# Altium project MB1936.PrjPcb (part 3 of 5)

## Sheet Power_MPU.SchDoc: Power MPU
size A3; Date: Not used; ApprovedBy: Not used; CheckedBy: Not used; Author: Not used; CompanyName: STMicroelectronics; DrawnBy: Not used; Engineer: Not used; Organization: Not used; Address1: Not used; Address2: Not used; Address3: Not used; Address4: Not used; DocumentNumber: Not used; Revision: Not used; SheetNumber: 5; SheetTotal: 18
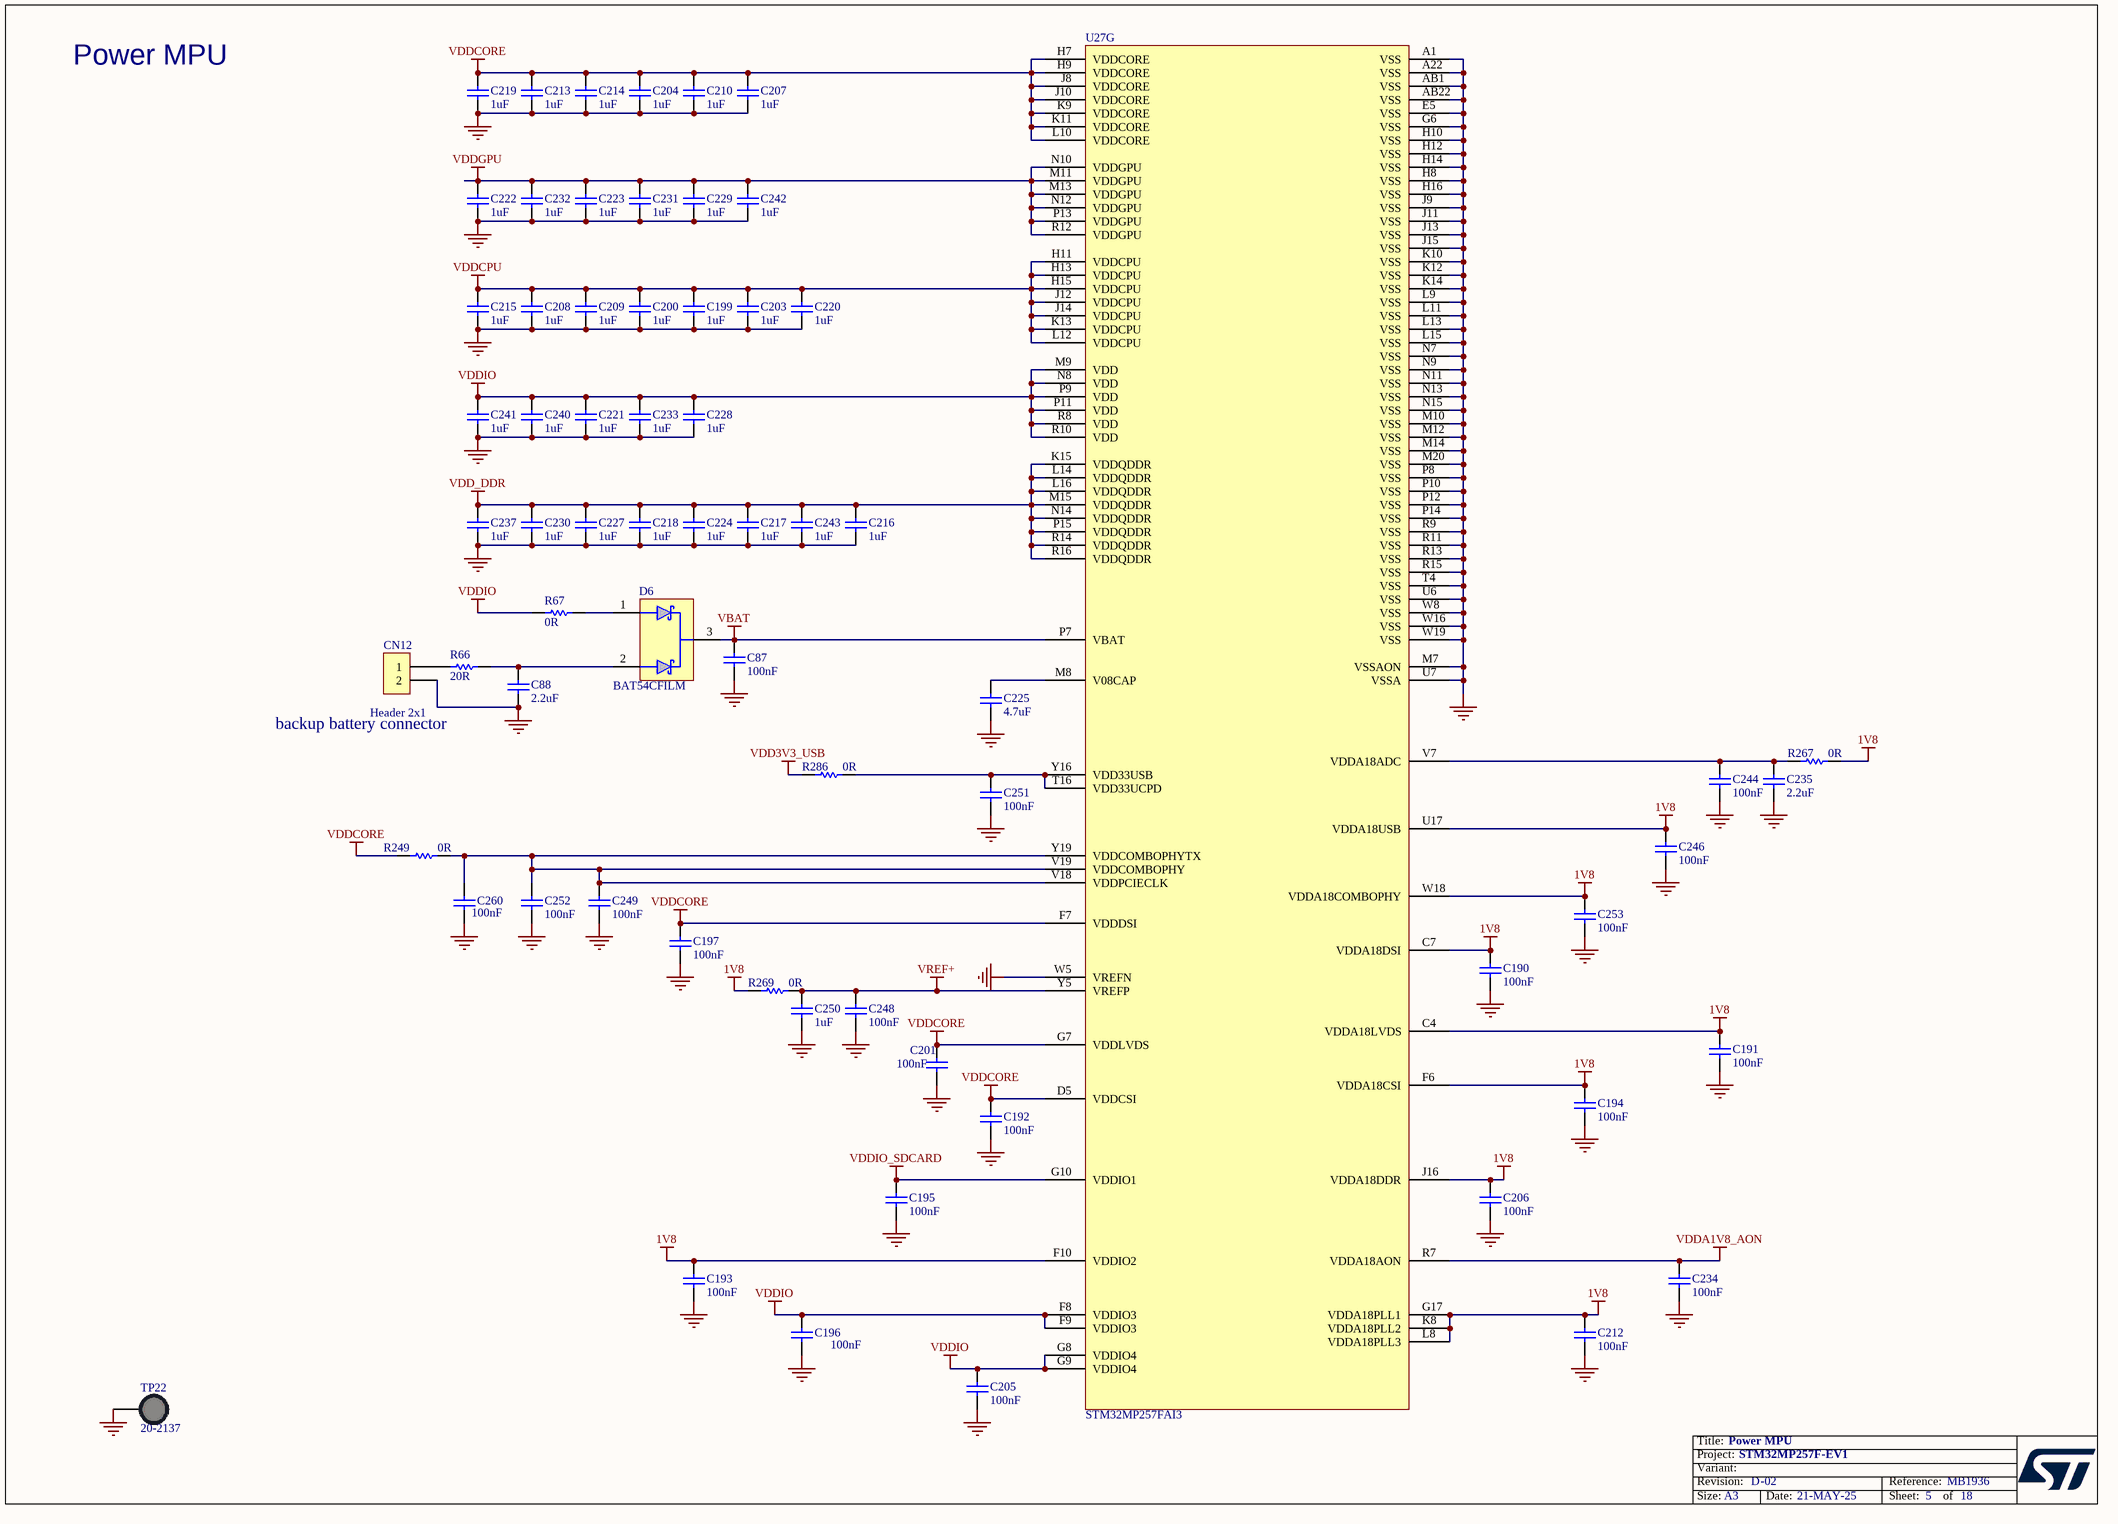
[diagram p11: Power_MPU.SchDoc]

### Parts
C87  value 100nF  [C0402]
C88  value 2.2uF  [C0402]  (hidden comment: Capacitor)
C190  value 100nF  [C0201_MURATA_GRM033_H0P3]  (hidden comment: Capacitor)
C191  value 100nF  [C0201_MURATA_GRM033_H0P3]  (hidden comment: Capacitor)
C192  value 100nF  [C0201_MURATA_GRM033_H0P3]  (hidden comment: Capacitor)
C193  value 100nF  [C0201_MURATA_GRM033_H0P3]  (hidden comment: Capacitor)
C194  value 100nF  [C0201_MURATA_GRM033_H0P3]  (hidden comment: Capacitor)
C195  value 100nF  [C0201_MURATA_GRM033_H0P3]  (hidden comment: Capacitor)
C196  value 100nF  [C0201_MURATA_GRM033_H0P3]  (hidden comment: Capacitor)
C197  value 100nF  [C0201_MURATA_GRM033_H0P3]  (hidden comment: Capacitor)
C199  value 1uF  [C0201_MURATA_GRM033_H0P3]  (hidden comment: Capacitor)
C200  value 1uF  [C0201_MURATA_GRM033_H0P3]  (hidden comment: Capacitor)
C201  value 100nF  [C0201_MURATA_GRM033_H0P3]  (hidden comment: Capacitor)
C203  value 1uF  [C0201_MURATA_GRM033_H0P3]  (hidden comment: Capacitor)
C204  value 1uF  [C0201_MURATA_GRM033_H0P3]  (hidden comment: Capacitor)
C205  value 100nF  [C0201_MURATA_GRM033_H0P3]  (hidden comment: Capacitor)
C206  value 100nF  [C0201_MURATA_GRM033_H0P3]  (hidden comment: Capacitor)
C207  value 1uF  [C0201_MURATA_GRM033_H0P3]  (hidden comment: Capacitor)
C208  value 1uF  [C0201_MURATA_GRM033_H0P3]  (hidden comment: Capacitor)
C209  value 1uF  [C0201_MURATA_GRM033_H0P3]  (hidden comment: Capacitor)
C210  value 1uF  [C0201_MURATA_GRM033_H0P3]  (hidden comment: Capacitor)
C212  value 100nF  [C0201_MURATA_GRM033_H0P3]  (hidden comment: Capacitor)
C213  value 1uF  [C0201_MURATA_GRM033_H0P3]  (hidden comment: Capacitor)
C214  value 1uF  [C0201_MURATA_GRM033_H0P3]  (hidden comment: Capacitor)
C215  value 1uF  [C0201_MURATA_GRM033_H0P3]  (hidden comment: Capacitor)
C216  value 1uF  [C0201_MURATA_GRM033_H0P3]  (hidden comment: Capacitor)
C217  value 1uF  [C0201_MURATA_GRM033_H0P3]  (hidden comment: Capacitor)
C218  value 1uF  [C0201_MURATA_GRM033_H0P3]  (hidden comment: Capacitor)
C219  value 1uF  [C0201_MURATA_GRM033_H0P3]  (hidden comment: Capacitor)
C220  value 1uF  [C0201_MURATA_GRM033_H0P3]  (hidden comment: Capacitor)
C221  value 1uF  [C0201_MURATA_GRM033_H0P3]  (hidden comment: Capacitor)
C222  value 1uF  [C0201_MURATA_GRM033_H0P3]  (hidden comment: Capacitor)
C223  value 1uF  [C0201_MURATA_GRM033_H0P3]  (hidden comment: Capacitor)
C224  value 1uF  [C0201_MURATA_GRM033_H0P3]  (hidden comment: Capacitor)
C225  value 4.7uF  [C0201_H0P5]  (hidden comment: Capacitor)
C227  value 1uF  [C0201_MURATA_GRM033_H0P3]  (hidden comment: Capacitor)
C228  value 1uF  [C0201_MURATA_GRM033_H0P3]  (hidden comment: Capacitor)
C229  value 1uF  [C0201_MURATA_GRM033_H0P3]  (hidden comment: Capacitor)
C230  value 1uF  [C0201_MURATA_GRM033_H0P3]  (hidden comment: Capacitor)
C231  value 1uF  [C0201_MURATA_GRM033_H0P3]  (hidden comment: Capacitor)
C232  value 1uF  [C0201_MURATA_GRM033_H0P3]  (hidden comment: Capacitor)
C233  value 1uF  [C0201_MURATA_GRM033_H0P3]  (hidden comment: Capacitor)
C234  value 100nF  [C0201_MURATA_GRM033_H0P3]  (hidden comment: Capacitor)
C235  value 2.2uF  [C0201_H0P5]  (hidden comment: Capacitor)
C237  value 1uF  [C0201_MURATA_GRM033_H0P3]  (hidden comment: Capacitor)
C240  value 1uF  [C0201_MURATA_GRM033_H0P3]  (hidden comment: Capacitor)
C241  value 1uF  [C0201_MURATA_GRM033_H0P3]  (hidden comment: Capacitor)
C242  value 1uF  [C0201_MURATA_GRM033_H0P3]  (hidden comment: Capacitor)
C243  value 1uF  [C0201_MURATA_GRM033_H0P3]  (hidden comment: Capacitor)
C244  value 100nF  [C0201_MURATA_GRM033_H0P3]  (hidden comment: Capacitor)
C246  value 100nF  [C0201_MURATA_GRM033_H0P3]  (hidden comment: Capacitor)
C248  value 100nF  [C0201_MURATA_GRM033_H0P3]  (hidden comment: Capacitor)
C249  value 100nF  [C0201_MURATA_GRM033_H0P3]  (hidden comment: Capacitor)
C250  value 1uF  [C0201_MURATA_GRM033_H0P3]  (hidden comment: Capacitor)
C251  value 100nF  [C0201_MURATA_GRM033_H0P3]  (hidden comment: Capacitor)
C252  value 100nF  [C0201_MURATA_GRM033_H0P3]  (hidden comment: Capacitor)
C253  value 100nF  [C0201_MURATA_GRM033_H0P3]  (hidden comment: Capacitor)
C260  value 100nF  [C0201_MURATA_GRM033_H0P3]  (hidden comment: Capacitor)
CN12  value Header 2x1  [CON_MOLEX_53047-0210]
D6  value BAT54CFILM  [DIO_SOT23]  (hidden comment: DIODE_3P_DUAL_COMMON_CATHODE)
R66  value 20R  [R0402]  (hidden comment: Resistor)
R67  value 0R  [R0402]  (hidden comment: Resistor)
R249  value 0R  [R0603]  (hidden comment: Resistor)
R267  value 0R  [R0402]
R269  value 0R  [R0402]
R286  value 0R  [R0402]
TP22  value 20-2137  [TP_PTH-1P02MM_TEST-TERMINAL_RS_101-2391_BLACK]  (hidden comment: Test_pin_conn_black)
U27  STM32MP257FAI3  [ICC_LFBGA436_18X18_P080_H1P70_STM32MP257_CODE-B0D1]  (part G of 9)

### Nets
1V8: C190.2 C191.2 C193.2 C194.2 C206.2 C212.2 C246.2 C253.2 R267.2 R269.1 U27.C4(VDDA18LVDS) U27.C7(VDDA18DSI) U27.F6(VDDA18CSI) U27.F10(VDDIO2) U27.G17(VDDA18PLL1) U27.J16(VDDA18DDR) U27.K8(VDDA18PLL2) U27.L8(VDDA18PLL3) U27.U17(VDDA18USB) U27.W18(VDDA18COMBOPHY)
GND: C87.1 C88.1 C190.1 C191.1 C192.1 C193.1 C194.1 C195.1 C196.1 C197.1 C199.1 C200.2 C201.1 C203.1 C204.2 C205.1 C206.1 C207.1 C208.1 C209.1 C210.1 C212.1 C213.1 C214.1 C215.2 C216.1 C217.1 C218.1 C219.2 C220.1 C221.1 C222.1 C223.1 C224.1 C225.1 C227.1 C228.1 C229.2 C230.2 C231.1 C232.1 C233.2 C234.1 C235.1 C237.1 C240.1 C241.2 C242.1 C243.1 C244.1 C246.1 C248.1 C249.1 C250.1 C251.1 C252.1 C253.1 C260.1 CN12.2 TP22.1 U27.A1(VSS) U27.A22(VSS) U27.AB1(VSS) U27.AB22(VSS) U27.E5(VSS) U27.G6(VSS) U27.H8(VSS) U27.H10(VSS) U27.H12(VSS) U27.H14(VSS) U27.H16(VSS) U27.J9(VSS) U27.J11(VSS) U27.J13(VSS) U27.J15(VSS) U27.K10(VSS) U27.K12(VSS) U27.K14(VSS) U27.L9(VSS) U27.L11(VSS) U27.L13(VSS) U27.L15(VSS) U27.M7(VSSAON) U27.M10(VSS) U27.M12(VSS) U27.M14(VSS) U27.M20(VSS) U27.N7(VSS) U27.N9(VSS) U27.N11(VSS) U27.N13(VSS) U27.N15(VSS) U27.P8(VSS) U27.P10(VSS) U27.P12(VSS) U27.P14(VSS) U27.R9(VSS) U27.R11(VSS) U27.R13(VSS) U27.R15(VSS) U27.T4(VSS) U27.U6(VSS) U27.U7(VSSA) U27.W5(VREFN) U27.W8(VSS) U27.W16(VSS) U27.W19(VSS)
VBAT: C87.2 D6.3 U27.P7(VBAT)
VDD3V3_USB: R286.1
VDD_DDR: C216.2 C217.2 C218.2 C224.2 C227.2 C230.1 C237.2 C243.2 U27.K15(VDDQDDR) U27.L14(VDDQDDR) U27.L16(VDDQDDR) U27.M15(VDDQDDR) U27.N14(VDDQDDR) U27.P15(VDDQDDR) U27.R14(VDDQDDR) U27.R16(VDDQDDR)
VDDA1V8_AON: C234.2 U27.R7(VDDA18AON)
VDDCORE: C192.2 C197.2 C201.2 C204.1 C207.2 C210.2 C213.2 C214.2 C219.1 R249.1 U27.D5(VDDCSI) U27.F7(VDDDSI) U27.G7(VDDLVDS) U27.H7(VDDCORE) U27.H9(VDDCORE) U27.J8(VDDCORE) U27.J10(VDDCORE) U27.K9(VDDCORE) U27.K11(VDDCORE) U27.L10(VDDCORE)
VDDCPU: C199.2 C200.1 C203.2 C208.2 C209.2 C215.1 C220.2 U27.H11(VDDCPU) U27.H13(VDDCPU) U27.H15(VDDCPU) U27.J12(VDDCPU) U27.J14(VDDCPU) U27.K13(VDDCPU) U27.L12(VDDCPU)
VDDGPU: C222.2 C223.2 C229.1 C231.2 C232.2 C242.2 U27.M11(VDDGPU) U27.M13(VDDGPU) U27.N10(VDDGPU) U27.N12(VDDGPU) U27.P13(VDDGPU) U27.R12(VDDGPU)
VDDIO: C196.2 C205.2 C221.2 C228.2 C233.1 C240.2 C241.1 R67.2 U27.F8(VDDIO3) U27.F9(VDDIO3) U27.G8(VDDIO4) U27.G9(VDDIO4) U27.M9(VDD) U27.N8(VDD) U27.P9(VDD) U27.P11(VDD) U27.R8(VDD) U27.R10(VDD)
VDDIO_SDCARD: C195.2 U27.G10(VDDIO1)
VREF+: C248.2 C250.2 R269.2 U27.Y5(VREFP)
NetC88_2: C88.2 D6.2 R66.2
NetC225_2: C225.2 U27.M8(V08CAP)
NetC235_2: C235.2 C244.2 R267.1 U27.V7(VDDA18ADC)
NetC249_2: C249.2 C252.2 C260.2 R249.2 U27.V18(VDDPCIECLK) U27.V19(VDDCOMBOPHY) U27.Y19(VDDCOMBOPHYTX)
NetC251_2: C251.2 R286.2 U27.T16(VDD33UCPD) U27.Y16(VDD33USB)
NetCN12_1: CN12.1 R66.1
NetD6_1: D6.1 R67.1

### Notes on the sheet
- Power MPU
- backup battery connector
- Title:
- Project:
- Size:
- Revision:
- Variant:
- A3
- -
- Date:
- Reference:
- Sheet:
- of

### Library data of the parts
C87 = MCD-00006: Capacitor,100nF,16V,X7R,10%,0402; Manufacturer_Part_Number: CC0402KRX7R7BB104; Manufacturer: YAGEO; Alternate_Manufacturer: MURATA; Alternate_Manufacturer_Part_Number: GCM155R71C104KA55D; Part_Preference: Recommended; Partial_Alternate_Internal_Part_Number: MCD-03299; Provided_By: SUBCO; Initial_Board_Reference: MB1274; Order_Code_RS: 9402047; Component_Country_Of_Origin: China; ID: 2474; ShowFields: YES
C88 = MCD-01823: Capacitor, MLCC, 2.2uF, 6V3, X5R,+/-10%, 0402, T=0.5mm; Part_Preference: Recommended; Manufacturer: MURATA; Manufacturer_Part_Number: GRM155R60J225KE95; Partial_Alternate_Internal_Part_Number: MCD-03566; Order_Code_RS: 172-6478; Component_Country_Of_Origin: Japan°°; ID: 3923; ShowFields: YES; Alternate_EMS: A
C190-C197 C201 C205 C206 C212 C234 C244 C246 C248 C249 C251-C253 C260 = MCD-01535: Capacitor, MLCC,100nF, 10V, X7R, +/-10%, 0201, T=0.3mm; Part_Preference: Recommended; Manufacturer: MURATA; Manufacturer_Part_Number: GRM033R61A104KE15; Order_Code_RS: 790-2742; Component_Country_Of_Origin: Japan°°; ID: 3635; ShowFields: YES
C199 C200 C203 C204 C207-C210 C213-C224 C227-C233 C237 C240-C243 C250 = MCD-02377: Capacitor, MLCC, 1uF, 6.3V, X5R, +/-20%, 0201, T=0,3mm; Manufacturer_Part_Number: GRM033R60J105MEA2; Manufacturer: MURATA; Part_Preference: Recommended; Partial_Alternate_Internal_Part_Number: MCD-04356; Order_Code_RS: 820-0643; Component_Country_Of_Origin: Japan°; ID: 4483; ShowFields: YES
C225 = MCD-01534: Capacitor, MLCC, 4,7uF, 6V3, X5R, +/-20%, 0201, T=0.5mm; Part_Preference: Recommended; Manufacturer: MURATA; Manufacturer_Part_Number: GRM035R60J475ME15; Component_Country_Of_Origin: Japan°°; ID: 3634; ShowFields: YES
C235 = MCD-02235: Capacitor, MLCC, 2.2uF, 10V, X5R,+/-10%, 0201, T=0.5mm; Part_Preference: Recommended; Manufacturer: MURATA; Manufacturer_Part_Number: GRM033R61A225KE47; Order_Code_RS: NA; Component_Country_Of_Origin: Japan°°; ShowFields: YES; ID: 4335
CN12 = MCD-00655: Header 2 circuits, 1.25mm Pitch ,  Vertical, with Friction Lock; Part_Type: Connector; Manufacturer_Part_Number: 53047-0210; Manufacturer: MOLEX; BMS_Part_Number: 9083002; Part_Preference: Recommended; Partial_Alternate_Internal_Part_Number: MCD-04371, MCD-04208; Provided_By: SUBCO; Initial_Board_Reference: MB1272; Order_Code_RS: 279-9213; Component_Country_Of_Origin: Unknown; ID: 3091; ShowFields: YES
D6 = MCD-03280: Diode, Schottky, Dual Common Cathode, 0V3, 300mA, 40V, SOT-23; Part_Preference: Recommended; Manufacturer: STMICROELECTRONICS; Order_code_RS: 795-8397; Component_Country_Of_Origin: China; ShowFields: YES; ID: 5396
R66 = MCD-00058: Resistor, 20R, 0402, +/-1%, 1/16W; BMS_Part_Number: 9131027; Part_Preference: Recommended; Manufacturer: YAGEO; Manufacturer_Part_Number: RC0402FR-0720RL; Order_Code_RS: 1799192; Component_Country_Of_Origin: China; ID: 2537; ShowFields: YES
R67 = MCD-00052: Resistor, 0R, 0402, +/-5%, 1/16W; Manufacturer_Part_Number: RC0402JR-070RL; Manufacturer: YAGEO; Part_Preference: Recommended; Order_Code_RS: 9232516RL; Component_Country_Of_Origin: China; ShowFields: YES; ID: 2540
R249 = MCD-00056: Resistor, 0R, 0603, +/-5%, 1/10W; Part_Preference: Recommended; Manufacturer: YAGEO; Manufacturer_Part_Number: RC0603JR-070RL; Order_Code_RS: 9233130RL; Component_Country_Of_Origin: China; ShowFields: YES; ID: 2536
R267 R269 R286 = MCD-00052: Resistor,0R,0402,5%,1/16W; Manufacturer_Part_Number: RC0402JR-070RL; Manufacturer: YAGEO; Part_Preference: Recommended; ECCN_US: EAR99; ECCN_EU: NEC; Provided_By: SUBCO; Initial_Board_Reference: mb1274; Order_Code_RS: 9232516RL; Component_Country_Of_Origin: China; ID: 2540; ShowFields: YES
TP22 = MCD-00713: Vero Technologies 1.02mm Black Terminal Post; Part_Type: Misc; Part_Preference: Recommended; Manufacturer_HQ_COO: Unknown; Partial_Alternate_Internal_Part_Number: MCD-04206, MCD-04594; Order_Code_RS: 101-2391; Provided_By: SUBCO; Component_Country_Of_Origin: UK; ID: 3032; ShowFields: YES
U27 = MCD-02000: MPU, ARM Cortex-A35 + M33 32-bit MPU, 808KB RAM, With Crypto; Part_Type: IC; Part_Preference: Recommended; Manufacturer: STMICROELECTRONICS; Manufacturer_HQ_COO: EU; Component_Country_Of_Origin: Unknown; ShowFields: YES; ID: 4100

## Sheet USB_HUB.SchDoc: USB_HUB
size A3; Date: Not used; ApprovedBy: Not used; CheckedBy: Not used; Author: Not used; CompanyName: STMicroelectronics; DrawnBy: Not used; Engineer: Not used; Organization: Not used; Address1: Not used; Address2: Not used; Address3: Not used; Address4: Not used; DocumentNumber: Not used; Revision: Not used; SheetNumber: 12; SheetTotal: 18
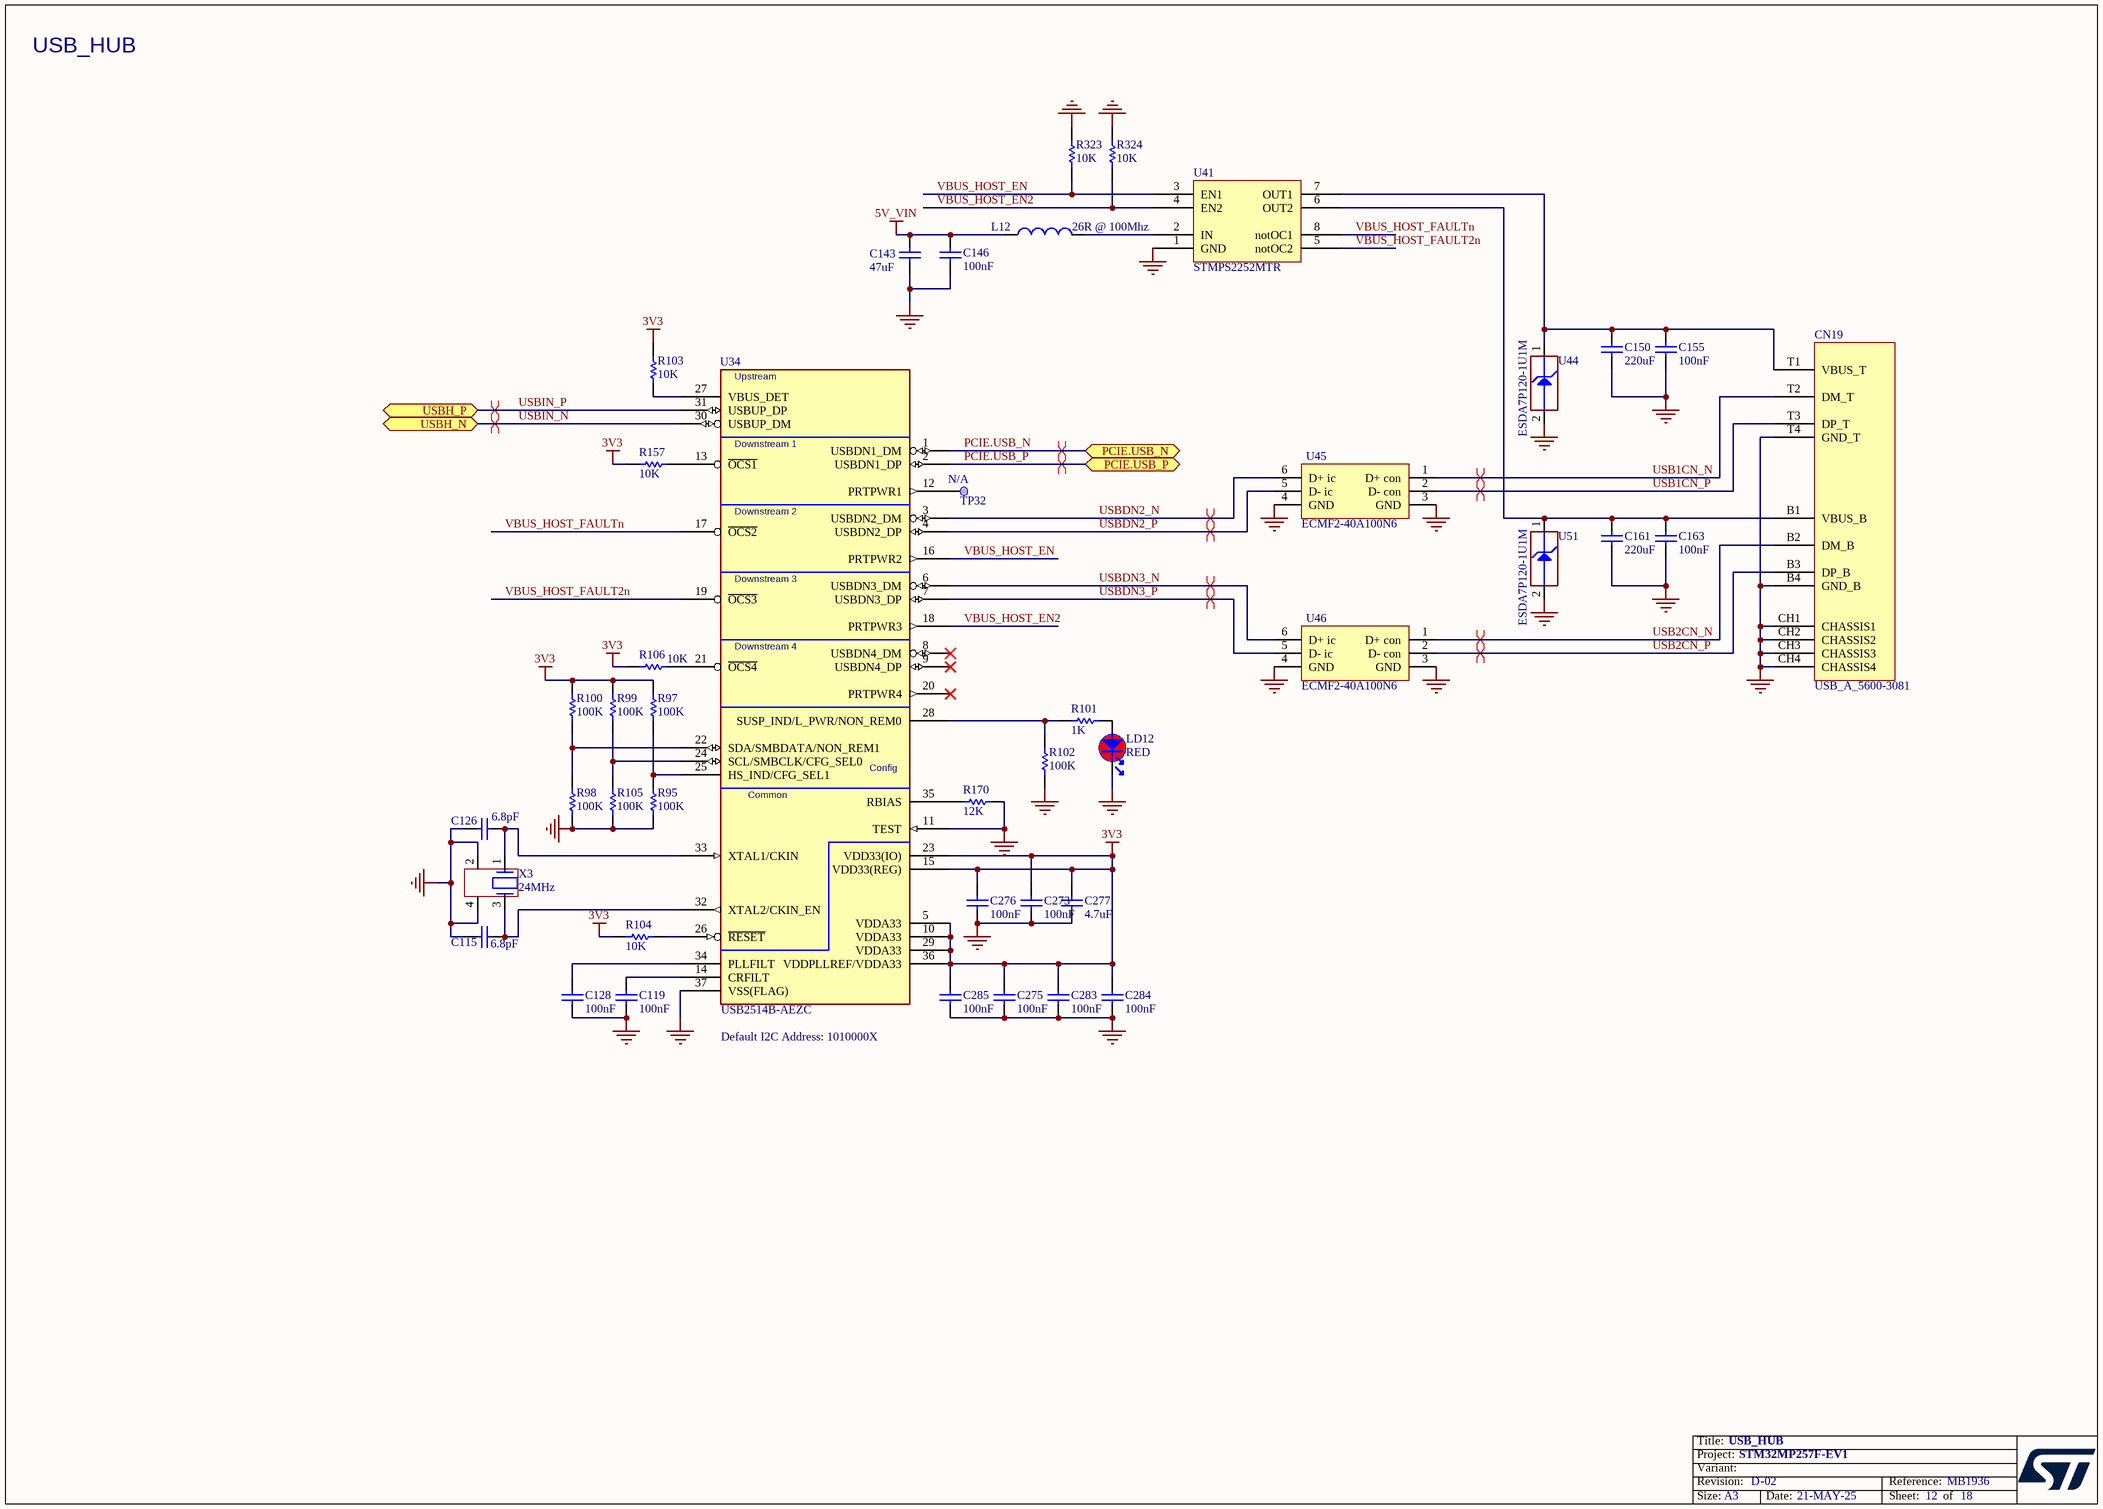
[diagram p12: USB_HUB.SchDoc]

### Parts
C115  value 6.8pF  [C0402]  (hidden comment: Capacitor)
C119  value 100nF  [C0402]  (hidden comment: Capacitor)
C126  value 6.8pF  [C0402]  (hidden comment: Capacitor)
C128  value 100nF  [C0402]  (hidden comment: Capacitor)
C143  value 47uF  [C0805]  (hidden comment: Capacitor)
C146  value 100nF  [C0402]  (hidden comment: Capacitor)
C150  value 220uF  [C1206_H1P6]  (hidden comment: Capacitor)
C155  value 100nF  [C0402]  (hidden comment: Capacitor)
C161  value 220uF  [C1206_H1P6]  (hidden comment: Capacitor)
C163  value 100nF  [C0402]  (hidden comment: Capacitor)
C273  value 100nF  [C0402]  (hidden comment: Capacitor)
C275  value 100nF  [C0402]  (hidden comment: Capacitor)
C276  value 100nF  [C0402]  (hidden comment: Capacitor)
C277  value 4.7uF  [C0402]  (hidden comment: Capacitor)
C283  value 100nF  [C0402]  (hidden comment: Capacitor)
C284  value 100nF  [C0402]  (hidden comment: Capacitor)
C285  value 100nF  [C0402]  (hidden comment: Capacitor)
CN19  value USB_A_5600-3081  [CON_DUAL-USB-TYPE-A_CONEXCON_5600-3081]  (hidden comment: USB_DUAL_TYPEA_5600-3081)
L12  value 26R @ 100Mhz  [FIL_0603_H0P65]  (hidden comment: BEAD)
LD12  value RED  [LED_0603_VISHAY_VLMS1300-GS08_RED_1A2K_H0P8]  (hidden comment: LED_red)
R95  value 100K  [R0402]  (hidden comment: Resistor)
R97  value 100K  [R0402]  (hidden comment: Resistor)
R98  value 100K  [R0402]  (hidden comment: Resistor)
R99  value 100K  [R0402]  (hidden comment: Resistor)
R100  value 100K  [R0402]  (hidden comment: Resistor)
R101  value 1K  [R0402]  (hidden comment: Resistor)
R102  value 100K  [R0402]  (hidden comment: Resistor)
R103  value 10K  [R0402]  (hidden comment: Resistor)
R104  value 10K  [R0402]  (hidden comment: Resistor)
R105  value 100K  [R0402]  (hidden comment: Resistor)
R106  value 10K  [R0402]  (hidden comment: Resistor)
R157  value 10K  [R0402]  (hidden comment: Resistor)
R170  value 12K  [R0402]  (hidden comment: Resistor)
R323  value 10K  [R0402]  (hidden comment: Resistor)
R324  value 10K  [R0402]  (hidden comment: Resistor)
TP32  Test Point  [TP_SMD_1MM]  (value not drawn)  (no BOM)
U34  USB2514B-AEZC  [ICC_QFN36-EPAD_6X6_P050]
U41  STMPS2252MTR  [ICC_SO8_5X4_P127]
U44  value ESDA7P120-1U1M  [ESD_QFN1610_2N_1K_2A]  (hidden comment: ESD-TRANSIL)
U45  ECMF2-40A100N6  [ESD_UQFN-6L_1P45X1P4_P040]
U46  ECMF2-40A100N6  [ESD_UQFN-6L_1P45X1P4_P040]
U51  value ESDA7P120-1U1M  [ESD_QFN1610_2N_1K_2A]  (hidden comment: ESD-TRANSIL)
X3  value 24MHz  [CRY_NX2016SA_4P]  (hidden comment: XTAL_4_PINS)

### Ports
PCIE.USB_N (bidir), PCIE.USB_P (bidir), USBH_N (bidir), USBH_P (bidir)

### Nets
3V3: C273.2 C275.2 C276.2 C277.2 C283.2 C284.2 C285.2 R97.2 R99.2 R100.2 R103.2 R104.1 R106.2 R157.2 U34.5(VDDA33) U34.10(VDDA33) U34.15(VDD33(REG)) U34.23(VDD33(IO)) U34.29(VDDA33) U34.36(VDDPLLREF/VDDA33)
5V_VIN: C143.2 C146.2 L12.1
GND: C115.1 C119.1 C126.1 C128.1 C143.1 C146.1 C150.1 C155.1 C161.1 C163.1 C273.1 C275.1 C276.1 C277.1 C283.1 C284.1 C285.1 CN19.B4(GND_B) CN19.CH1(CHASSIS1) CN19.CH2(CHASSIS2) CN19.CH3(CHASSIS3) CN19.CH4(CHASSIS4) CN19.T4(GND_T) LD12.2 R95.1 R98.1 R102.1 R105.1 R170.1 R323.1 R324.1 U34.11(TEST) U34.37(VSS(FLAG)) U41.1(GND) U44.2(GND) U45.3(GND) U45.4(GND) U46.3(GND) U46.4(GND) U51.2(GND) X3.2 X3.4
PCIE.USB_N: U34.1(USBDN1_DM) ; port PCIE.USB_N
PCIE.USB_P: U34.2(USBDN1_DP) ; port PCIE.USB_P
USB1CN_N: CN19.T2(DM_T) U45.1(D+_con)
USB1CN_P: CN19.T3(DP_T) U45.2(D-_con)
USB2CN_N: CN19.B2(DM_B) U46.1(D+_con)
USB2CN_P: CN19.B3(DP_B) U46.2(D-_con)
USBDN2_N: U34.3(USBDN2_DM) U45.6(D+_ic)
USBDN2_P: U34.4(USBDN2_DP) U45.5(D-_ic)
USBDN3_N: U34.6(USBDN3_DM) U46.6(D+_ic)
USBDN3_P: U34.7(USBDN3_DP) U46.5(D-_ic)
USBIN_N: U34.30(USBUP_DM) ; port USBH_N  [project net USBH_N]
USBIN_P: U34.31(USBUP_DP) ; port USBH_P  [project net USBH_P]
VBUS_HOST_EN: R323.2 U34.16(PRTPWR2) U41.3(EN1)
VBUS_HOST_EN2: R324.2 U34.18(PRTPWR3) U41.4(EN2)
VBUS_HOST_FAULT2n: U34.19(~{OCS3}) U41.5(notOC2)
VBUS_HOST_FAULTn: U34.17(~{OCS2}) U41.8(notOC1)
NetC115_2: C115.2 U34.32(XTAL2/CKIN_EN) X3.3
NetC119_2: C119.2 U34.14(CRFILT)
NetC126_2: C126.2 U34.33(XTAL1/CKIN) X3.1
NetC128_2: C128.2 U34.34(PLLFILT)
NetC150_2: C150.2 C155.2 CN19.T1(VBUS_T) U41.7(OUT1) U44.1(IO1)
NetC161_2: C161.2 C163.2 CN19.B1(VBUS_B) U41.6(OUT2) U51.1(IO1)
NetL12_2: L12.2 U41.2(IN)
NetLD12_1: LD12.1 R101.1
NetR95_2: R95.2 R97.1 U34.25(HS_IND/CFG_SEL1)
NetR98_2: R98.2 R100.1 U34.22(SDA/SMBDATA/NON_REM1)
NetR99_1: R99.1 R105.2 U34.24(SCL/SMBCLK/CFG_SEL0)
NetR101_2: R101.2 R102.2 U34.28(SUSP_IND/L_PWR/NON_REM0)
NetR103_1: R103.1 U34.27(VBUS_DET)
NetR104_2: R104.2 U34.26(~{RESET})
NetR106_1: R106.1 U34.21(~{OCS4})
NetR157_1: R157.1 U34.13(~{OCS1})
NetR170_2: R170.2 U34.35(RBIAS)
NetTP32_1: TP32.1 U34.12(PRTPWR1)

Not connected (* = marked no-connect by the designer): U34 8(USBDN4_DM)* 9(USBDN4_DP)* 20(PRTPWR4)*

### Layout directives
differential pair: PCIE.USB_N, PCIE.USB_P, USB1CN_N, USB1CN_P, USB2CN_N, USB2CN_P, USBDN2_N, USBDN2_P, USBDN3_N, USBDN3_P, USBH_N, USBH_P

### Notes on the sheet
- USB_HUB
- Default I2C Address: 1010000X

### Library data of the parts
C115 C126 = MCD-00674: Capacitor, MLCC, 6.8pF, 50V, NPO, +/-0.25pF, 0402, T=0.5mm; Manufacturer_Part_Number: CC0402CRNPO9BN6R8; Manufacturer: YAGEO; Part_Preference: Recommended; Component_Country_Of_Origin: China; ID: 3068; ShowFields: YES
C119 C128 C146 C155 C163 C273 C275 C276 C283-C285 = MCD-00006: Capacitor, MLCC, 100nF, 16V, X7R, +/-10%, 0402, T=0.5mm; Manufacturer_Part_Number: CC0402KRX7R7BB104; Manufacturer: YAGEO; Part_Preference: Recommended; Partial_Alternate_Internal_Part_Number: MCD-03299; Order_Code_RS: 9402047; Component_Country_Of_Origin: China; ID: 2474; ShowFields: YES
C143 = MCD-00204: Capacitor, MLCC, 47uF, 10V, X5R, +/-20%, 0805, T=1.25mm; Part_Preference: Recommended; Manufacturer: MURATA; Manufacturer_Part_Number: GRM21BR61A476ME15; Component_Country_Of_Origin: Japan°°; ShowFields: YES; ID: 2664
C150 C161 = MCD-00104: Capacitor, MLCC, 220uF, 6V3, X5R, +/-20%, 1206, T=1.6mm; Manufacturer_Part_Number: GRM31CR60J227ME11; Manufacturer: MURATA; Part_Preference: Recommended; Order_Code_RS: 170-6396; Component_Country_Of_Origin: Japan°°; ID: 2764; ShowFields: YES
C277 = MCD-01356: Capacitor, MLCC, 4.7uF, 6V3, X5R, +/-20%, 0402, T=0.5mm; Manufacturer_Part_Number: GRM155R60J475ME47; Manufacturer: MURATA; Part_Preference: Recommended; Partial_Alternate_Internal_Part_Number: MCD-04455; Order_Code_RS: 814-5230; Component_Country_Of_Origin: Japan°°; ID: 3456; ShowFields: YES
CN19 = MCD-00109: USB_Dual-TypeA, Receptacle, 8pins, 2.5mm, RA, TH, T= 15.5mm; Manufacturer: CONEXCON; Part_Type: Connector; Part_Preference: Recommended; Partial_Alternate_Internal_Part_Number: MCD-04367; Component_Country_Of_Origin: Unknown; ID: 2756; ShowFields: YES
L12 = MCD-00305: Ferrite bead, 26R @ 100Mhz, +/-25%, 6000mA, 0R007, 0603, T=0.75mm; Manufacturer_Part_Number: BLM18KG260TN1; Manufacturer: MURATA; Part_Type: Inductor; Part_Preference: Recommended; Order_Code_RS: 747-4723; Component_Country_Of_Origin: Japan°°; ID: 2564; ShowFields: YES
LD12 = MCD-00587: LED Red, 0603 SMD, 2V Forward Voltage; Part_Type: Display; Manufacturer_Part_Number: VLMS1300-GS08; Manufacturer: VISHAY; Alternate_Manufacturer_Part_Number: LS Q976-NR-1; Alternate_Manufacturer: OSRAM OPTO SEMICONDUCTORS; Alternate_Internal_Part_Number: MCD-02401; Part_Preference: Recommended; Partial_Alternate_Internal_Part_Number: MCD-03983; Provided_By: SUBCO; Component_Country_Of_Origin: China; ID: 3154; ShowFields: YES
R95 R97-R100 R102 R105 = MCD-00059: Resistor, 100K, 0402, +/-1%, 1/16W; Manufacturer_Part_Number: RC0402FR-07100KL; Manufacturer: YAGEO; Part_Preference: Recommended; Partial_Alternate_Internal_Part_Number: MCD-03301; Order_Code_RS: 2421891; Component_Country_Of_Origin: China; ID: 2533; ShowFields: YES
R101 = MCD-00061: Resistor, 1K, 0402, +/-1%,1/16W; Manufacturer_Part_Number: RC0402FR-071KL; Manufacturer: YAGEO; Part_Preference: Recommended; Order_Code_RS: 9239235; Component_Country_Of_Origin: China; ID: 2532; ShowFields: YES
R103 R104 R106 R157 R323 R324 = MCD-00053: Resistor, 10K, 0402, +/-1%, 1/16W; Manufacturer_Part_Number: RC0402FR-0710KL; Manufacturer: YAGEO; BMS_Part_Number: 9131590; Part_Preference: Recommended; Order_Code_RS: 9239359; Component_Country_Of_Origin: China; ID: 2539; ShowFields: YES
R170 = MCD-00187: Resistor, 12K, 0402, +/-1%, 1/16W; Manufacturer_Part_Number: RC0402FR-0712KL; Manufacturer: YAGEO; BMS_Part_Number: 9131030; Part_Preference: Recommended; Component_Country_Of_Origin: China; ID: 2678; ShowFields: YES
TP32 = MCD-00074: Test Point 1mm; Part_Type: Misc; Part_Preference: Recommended; Component_Country_Of_Origin: Unknown; ID: 2518; ShowFields: YES
U34 = MCD-00145: USB HUB 2,0 Controller; Manufacturer: MICROCHIP; Part_Type: IC; Part_Preference: Recommended; Component_Country_Of_Origin: Unknown; Order_Code_RS: 772-9464; ID: 2724; ShowFields: YES
U41 = MCD-00123: IC,Dual-Channel-Power-Switch,500mA,100mR,SO8; Manufacturer: STMICROELECTRONICS; BMS_Part_Number: 9159012; Part_Preference: Recommended; Manufacturer_HQ_COO: EU; Component_Country_Of_Origin: China; ID: 2746; ShowFields: YES
U44 U51 = MCD-01026: High power transient voltage suppressor; Part_Type: Diode; Manufacturer: STMICROELECTRONICS; BMS_Part_Number: 9179046; Part_Preference: Recommended; Manufacturer_HQ_COO: EU; Component_Country_Of_Origin: China; Order_Code_RS: 190-7605; ID: 2997; ShowFields: YES
U45 U46 = MCD-03060: ESD protection & Common Filter High Speed serial Interfaces , 0.4 pitch; Part_Type: IC; Part_Preference: Recommended; Manufacturer: STMICROELECTRONICS; ShowFields: YES; ID: 5176; Component_Country_Of_Origin: China
X3 = MCD-01036: Crystal, 24MHz, 6pF, +/-20ppm, 80R, 2x1.6mm; Part_Type: Crystal_Osc; Manufacturer_Part_Number: NX2016SA-24MHZ-EXS00A-CS10820; Manufacturer: NDK; BMS_Part_Number: 9157045; Part_Preference: Recommended; Component_Country_Of_Origin: Japan; ID: 2989; ShowFields: YES

## Sheet 2_DDR4_16bits.SchDoc: 2 DDR4 16 bits
size A3; Date: Not used; ApprovedBy: Not used; CheckedBy: Not used; Author: Not used; CompanyName: STMicroelectronics; DrawnBy: Not used; Engineer: Not used; Organization: Not used; Address1: Not used; Address2: Not used; Address3: Not used; Address4: Not used; DocumentNumber: Not used; Revision: Not used; SheetNumber: 6; SheetTotal: 18
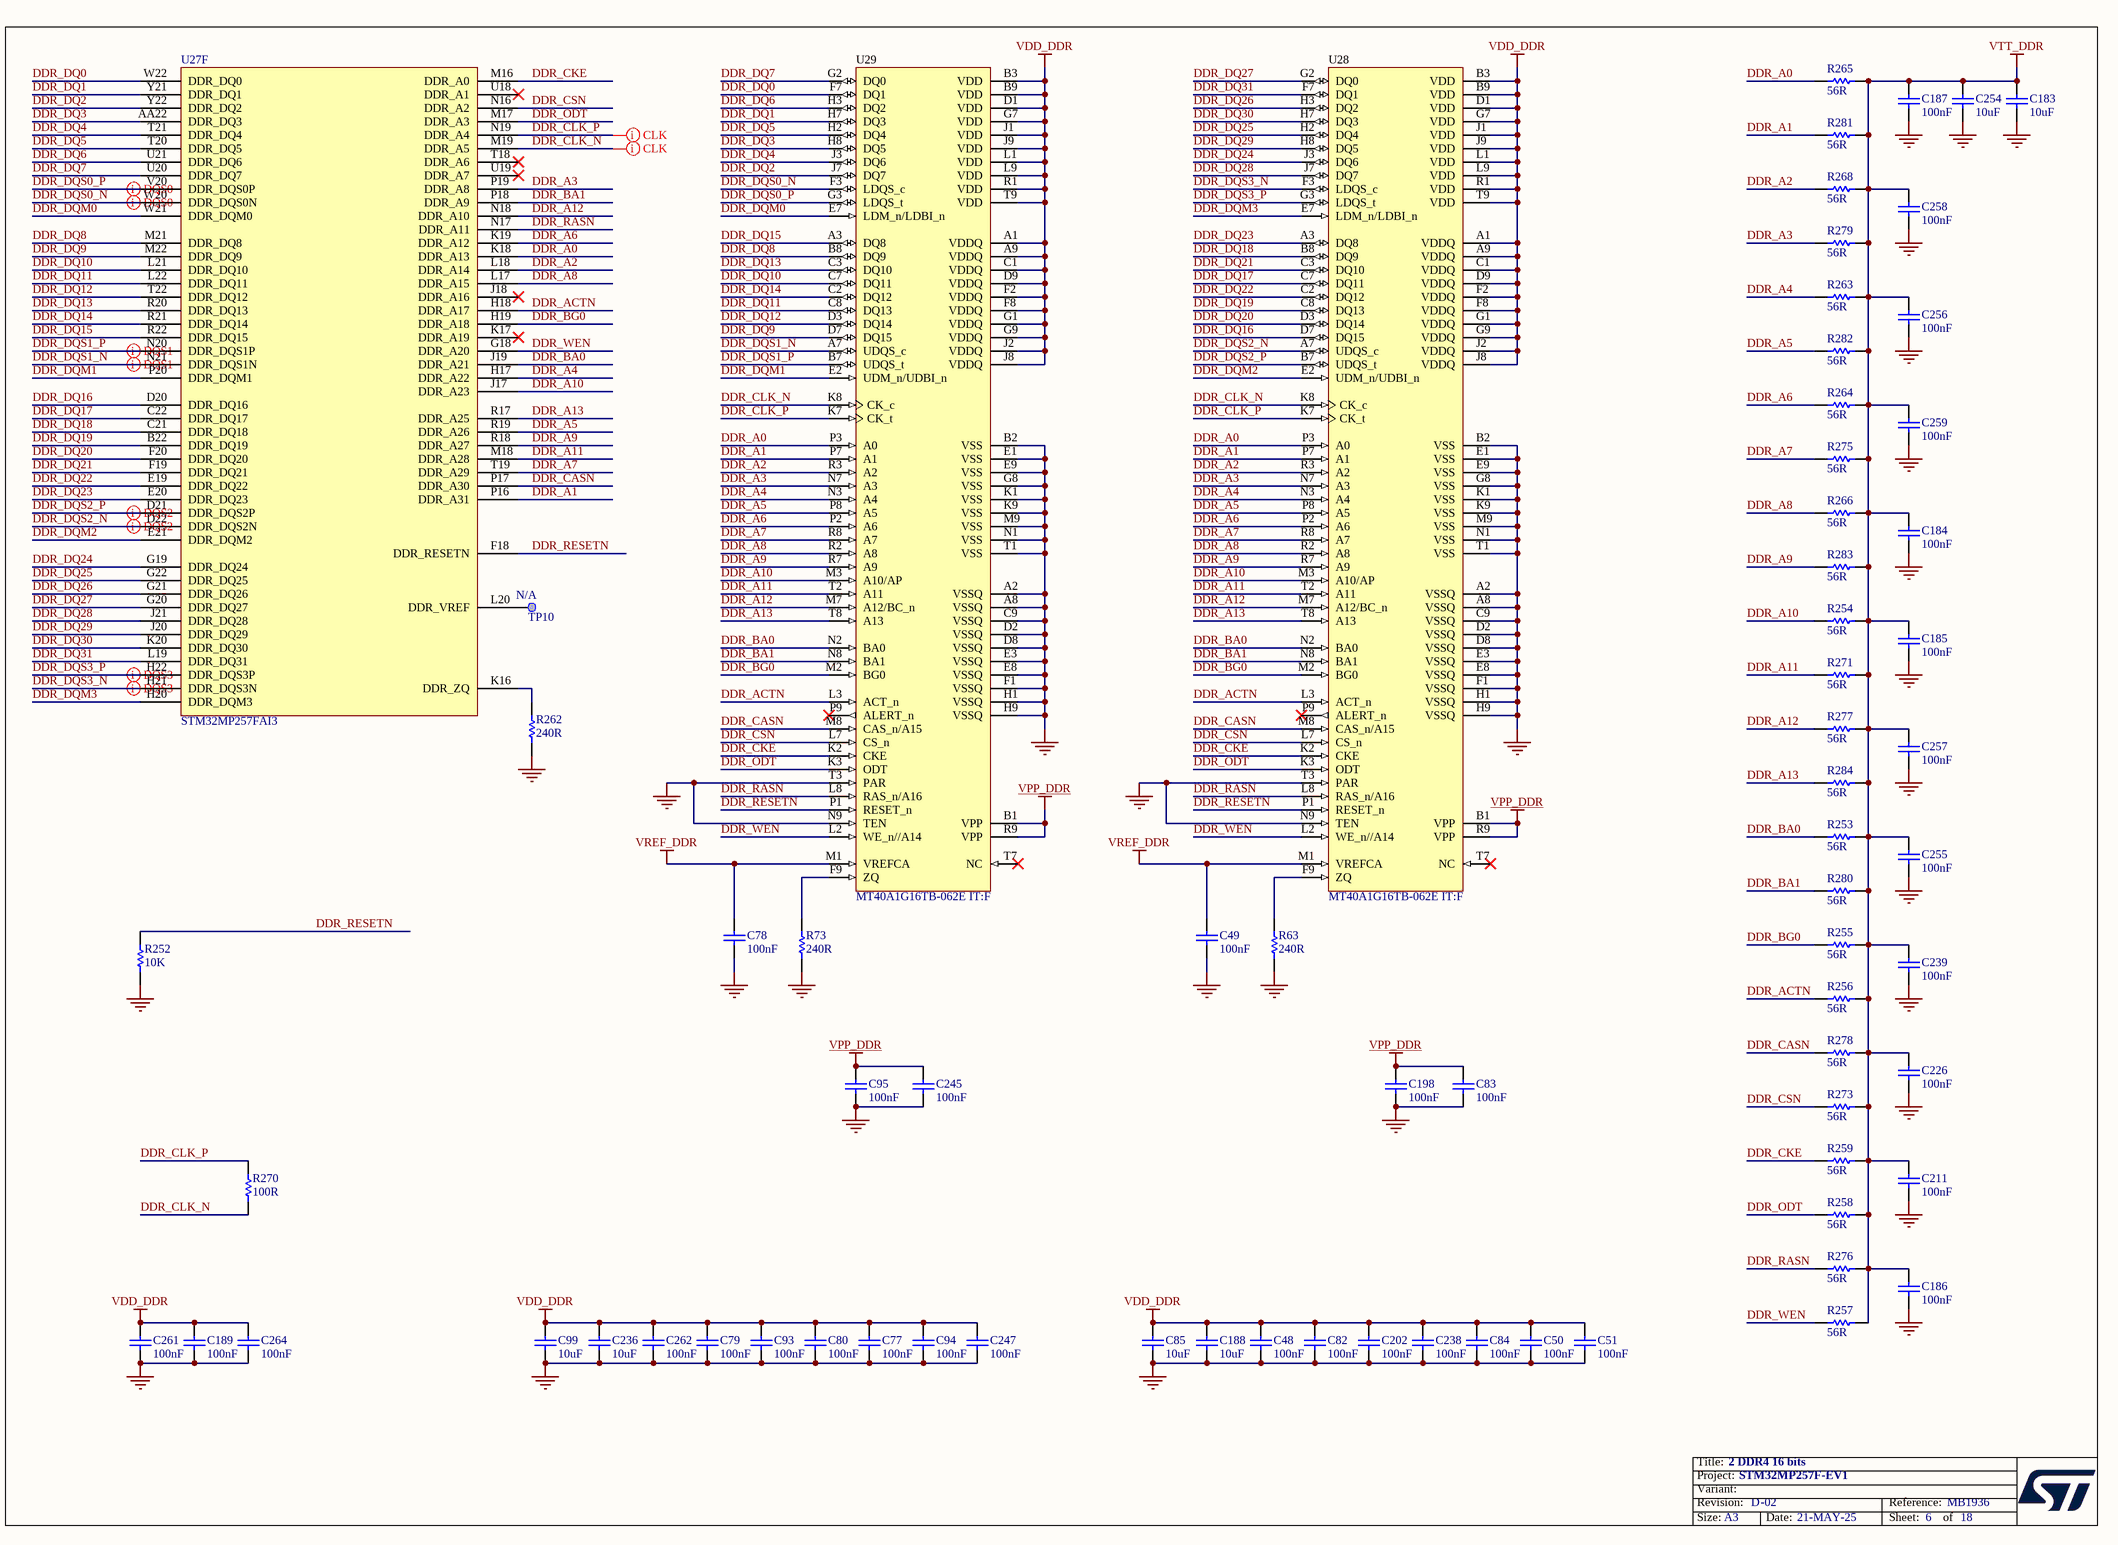
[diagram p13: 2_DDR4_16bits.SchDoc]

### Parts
C48  value 100nF  [C0402]  (hidden comment: Capacitor)
C49  value 100nF  [C0402]  (hidden comment: Capacitor)
C50  value 100nF  [C0402]  (hidden comment: Capacitor)
C51  value 100nF  [C0402]  (hidden comment: Capacitor)
C77  value 100nF  [C0402]  (hidden comment: Capacitor)
C78  value 100nF  [C0402]  (hidden comment: Capacitor)
C79  value 100nF  [C0402]  (hidden comment: Capacitor)
C80  value 100nF  [C0402]  (hidden comment: Capacitor)
C82  value 100nF  [C0402]  (hidden comment: Capacitor)
C83  value 100nF  [C0402]  (hidden comment: Capacitor)
C84  value 100nF  [C0402]  (hidden comment: Capacitor)
C85  value 10uF  [C0603]  (hidden comment: Capacitor)
C93  value 100nF  [C0402]  (hidden comment: Capacitor)
C94  value 100nF  [C0402]  (hidden comment: Capacitor)
C95  value 100nF  [C0402]  (hidden comment: Capacitor)
C99  value 10uF  [C0603]  (hidden comment: Capacitor)
C183  value 10uF  [C0603]  (hidden comment: Capacitor)
C184  value 100nF  [C0402]  (hidden comment: Capacitor)
C185  value 100nF  [C0402]  (hidden comment: Capacitor)
C186  value 100nF  [C0402]  (hidden comment: Capacitor)
C187  value 100nF  [C0402]  (hidden comment: Capacitor)
C188  value 10uF  [C0603]  (hidden comment: Capacitor)
C189  value 100nF  [C0402]  (hidden comment: Capacitor)
C198  value 100nF  [C0402]  (hidden comment: Capacitor)
C202  value 100nF  [C0402]  (hidden comment: Capacitor)
C211  value 100nF  [C0402]  (hidden comment: Capacitor)
C226  value 100nF  [C0402]  (hidden comment: Capacitor)
C236  value 10uF  [C0603]  (hidden comment: Capacitor)
C238  value 100nF  [C0402]  (hidden comment: Capacitor)
C239  value 100nF  [C0402]  (hidden comment: Capacitor)
C245  value 100nF  [C0402]  (hidden comment: Capacitor)
C247  value 100nF  [C0402]  (hidden comment: Capacitor)
C254  value 10uF  [C0603]  (hidden comment: Capacitor)
C255  value 100nF  [C0402]  (hidden comment: Capacitor)
C256  value 100nF  [C0402]  (hidden comment: Capacitor)
C257  value 100nF  [C0402]  (hidden comment: Capacitor)
C258  value 100nF  [C0402]  (hidden comment: Capacitor)
C259  value 100nF  [C0402]  (hidden comment: Capacitor)
C261  value 100nF  [C0402]  (hidden comment: Capacitor)
C262  value 100nF  [C0402]  (hidden comment: Capacitor)
C264  value 100nF  [C0402]  (hidden comment: Capacitor)
R63  value 240R  [R0201_H0P23]  (hidden comment: Resistor)
R73  value 240R  [R0201_H0P23]  (hidden comment: Resistor)
R252  value 10K  [R0402]  (hidden comment: Resistor)
R253  value 56R  [R0402]  (hidden comment: Resistor)
R254  value 56R  [R0402]  (hidden comment: Resistor)
R255  value 56R  [R0402]  (hidden comment: Resistor)
R256  value 56R  [R0402]  (hidden comment: Resistor)
R257  value 56R  [R0402]  (hidden comment: Resistor)
R258  value 56R  [R0402]  (hidden comment: Resistor)
R259  value 56R  [R0402]  (hidden comment: Resistor)
R262  value 240R  [R0201_H0P23]  (hidden comment: Resistor)
R263  value 56R  [R0402]  (hidden comment: Resistor)
R264  value 56R  [R0402]  (hidden comment: Resistor)
R265  value 56R  [R0402]  (hidden comment: Resistor)
R266  value 56R  [R0402]  (hidden comment: Resistor)
R268  value 56R  [R0402]  (hidden comment: Resistor)
R270  value 100R  [R0402]  (hidden comment: Resistor)
R271  value 56R  [R0402]  (hidden comment: Resistor)
R273  value 56R  [R0402]  (hidden comment: Resistor)
R275  value 56R  [R0402]  (hidden comment: Resistor)
R276  value 56R  [R0402]  (hidden comment: Resistor)
R277  value 56R  [R0402]  (hidden comment: Resistor)
R278  value 56R  [R0402]  (hidden comment: Resistor)
R279  value 56R  [R0402]  (hidden comment: Resistor)
R280  value 56R  [R0402]  (hidden comment: Resistor)
R281  value 56R  [R0402]  (hidden comment: Resistor)
R282  value 56R  [R0402]  (hidden comment: Resistor)
R283  value 56R  [R0402]  (hidden comment: Resistor)
R284  value 56R  [R0402]  (hidden comment: Resistor)
TP10  Test Point  [TP_SMD_0-6MM]  (value not drawn)  (no BOM)
U27  STM32MP257FAI3  [ICC_LFBGA436_18X18_P080_H1P70_STM32MP257_CODE-B0D1]  (part F of 9)
U28  MT40A1G16TB-062E IT:F  [ICC_FBGA96_TB_7P5X13_P080]
U29  MT40A1G16TB-062E IT:F  [ICC_FBGA96_TB_7P5X13_P080]

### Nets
GND: C48.1 C49.1 C50.1 C51.1 C77.1 C78.1 C79.1 C80.1 C82.1 C83.1 C84.1 C85.1 C93.1 C94.1 C95.1 C99.1 C183.1 C184.1 C185.1 C186.1 C187.1 C188.1 C189.1 C198.1 C202.1 C211.1 C226.1 C236.1 C238.1 C239.1 C245.1 C247.1 C254.1 C255.1 C256.1 C257.1 C258.1 C259.1 C261.1 C262.1 C264.1 R63.1 R73.1 R252.1 R262.1 U28.A2(VSSQ) U28.A8(VSSQ) U28.B2(VSS) U28.C9(VSSQ) U28.D2(VSSQ) U28.D8(VSSQ) U28.E1(VSS) U28.E3(VSSQ) U28.E8(VSSQ) U28.E9(VSS) U28.F1(VSSQ) U28.G8(VSS) U28.H1(VSSQ) U28.H9(VSSQ) U28.K1(VSS) U28.K9(VSS) U28.M9(VSS) U28.N1(VSS) U28.N9(TEN) U28.T1(VSS) U28.T3(PAR) U29.A2(VSSQ) U29.A8(VSSQ) U29.B2(VSS) U29.C9(VSSQ) U29.D2(VSSQ) U29.D8(VSSQ) U29.E1(VSS) U29.E3(VSSQ) U29.E8(VSSQ) U29.E9(VSS) U29.F1(VSSQ) U29.G8(VSS) U29.H1(VSSQ) U29.H9(VSSQ) U29.K1(VSS) U29.K9(VSS) U29.M9(VSS) U29.N1(VSS) U29.N9(TEN) U29.T1(VSS) U29.T3(PAR)
VDD_DDR: C48.2 C50.2 C51.2 C77.2 C79.2 C80.2 C82.2 C84.2 C85.2 C93.2 C94.2 C99.2 C188.2 C189.2 C202.2 C236.2 C238.2 C247.2 C261.2 C262.2 C264.2 U28.A1(VDDQ) U28.A9(VDDQ) U28.B3(VDD) U28.B9(VDD) U28.C1(VDDQ) U28.D1(VDD) U28.D9(VDDQ) U28.F2(VDDQ) U28.F8(VDDQ) U28.G1(VDDQ) U28.G7(VDD) U28.G9(VDDQ) U28.J1(VDD) U28.J2(VDDQ) U28.J8(VDDQ) U28.J9(VDD) U28.L1(VDD) U28.L9(VDD) U28.R1(VDD) U28.T9(VDD) U29.A1(VDDQ) U29.A9(VDDQ) U29.B3(VDD) U29.B9(VDD) U29.C1(VDDQ) U29.D1(VDD) U29.D9(VDDQ) U29.F2(VDDQ) U29.F8(VDDQ) U29.G1(VDDQ) U29.G7(VDD) U29.G9(VDDQ) U29.J1(VDD) U29.J2(VDDQ) U29.J8(VDDQ) U29.J9(VDD) U29.L1(VDD) U29.L9(VDD) U29.R1(VDD) U29.T9(VDD)
VPP_DDR: C83.2 C95.2 C198.2 C245.2 U28.B1(VPP) U28.R9(VPP) U29.B1(VPP) U29.R9(VPP)
VREF_DDR: C49.2 C78.2 U28.M1(VREFCA) U29.M1(VREFCA)
VTT_DDR: C183.2 C184.2 C185.2 C186.2 C187.2 C211.2 C226.2 C239.2 C254.2 C255.2 C256.2 C257.2 C258.2 C259.2 R253.2 R254.2 R255.2 R256.2 R257.2 R258.2 R259.2 R263.2 R264.2 R265.2 R266.2 R268.2 R271.2 R273.2 R275.2 R276.2 R277.2 R278.2 R279.2 R280.2 R281.2 R282.2 R283.2 R284.2
DDR_A0: R265.1 U27.K18(DDR_A13) U28.P3(A0) U29.P3(A0)
DDR_A1: R281.1 U27.P16(DDR_A31) U28.P7(A1) U29.P7(A1)
DDR_A2: R268.1 U27.L18(DDR_A14) U28.R3(A2) U29.R3(A2)
DDR_A3: R279.1 U27.P19(DDR_A8) U28.N7(A3) U29.N7(A3)
DDR_A4: R263.1 U27.H17(DDR_A22) U28.N3(A4) U29.N3(A4)
DDR_A5: R282.1 U27.R19(DDR_A26) U28.P8(A5) U29.P8(A5)
DDR_A6: R264.1 U27.K19(DDR_A12) U28.P2(A6) U29.P2(A6)
DDR_A7: R275.1 U27.T19(DDR_A29) U28.R8(A7) U29.R8(A7)
DDR_A8: R266.1 U27.L17(DDR_A15) U28.R2(A8) U29.R2(A8)
DDR_A9: R283.1 U27.R18(DDR_A27) U28.R7(A9) U29.R7(A9)
DDR_A10: R254.1 U27.J17(DDR_A23) U28.M3(A10/AP) U29.M3(A10/AP)
DDR_A11: R271.1 U27.M18(DDR_A28) U28.T2(A11) U29.T2(A11)
DDR_A12: R277.1 U27.N18(DDR_A10) U28.M7(A12/BC_n) U29.M7(A12/BC_n)
DDR_A13: R284.1 U27.R17(DDR_A25) U28.T8(A13) U29.T8(A13)
DDR_ACTN: R256.1 U27.H18(DDR_A17) U28.L3(ACT_n) U29.L3(ACT_n)
DDR_BA0: R253.1 U27.J19(DDR_A21) U28.N2(BA0) U29.N2(BA0)
DDR_BA1: R280.1 U27.P18(DDR_A9) U28.N8(BA1) U29.N8(BA1)
DDR_BG0: R255.1 U27.H19(DDR_A18) U28.M2(BG0) U29.M2(BG0)
DDR_CASN: R278.1 U27.P17(DDR_A30) U28.M8(CAS_n/A15) U29.M8(CAS_n/A15)
DDR_CKE: R259.1 U27.M16(DDR_A0) U28.K2(CKE) U29.K2(CKE)
DDR_CLK_N: R270.2 U27.M19(DDR_A5) U28.K8(CK_c) U29.K8(CK_c)
DDR_CLK_P: R270.1 U27.N19(DDR_A4) U28.K7(CK_t) U29.K7(CK_t)
DDR_CSN: R273.1 U27.N16(DDR_A2) U28.L7(CS_n) U29.L7(CS_n)
DDR_DQ0: U27.W22(DDR_DQ0) U29.F7(DQ1)
DDR_DQ1: U27.Y21(DDR_DQ1) U29.H7(DQ3)
DDR_DQ2: U27.Y22(DDR_DQ2) U29.J7(DQ7)
DDR_DQ3: U27.AA22(DDR_DQ3) U29.H8(DQ5)
DDR_DQ4: U27.T21(DDR_DQ4) U29.J3(DQ6)
DDR_DQ5: U27.T20(DDR_DQ5) U29.H2(DQ4)
DDR_DQ6: U27.U21(DDR_DQ6) U29.H3(DQ2)
DDR_DQ7: U27.U20(DDR_DQ7) U29.G2(DQ0)
DDR_DQ8: U27.M21(DDR_DQ8) U29.B8(DQ9)
DDR_DQ9: U27.M22(DDR_DQ9) U29.D7(DQ15)
DDR_DQ10: U27.L21(DDR_DQ10) U29.C7(DQ11)
DDR_DQ11: U27.L22(DDR_DQ11) U29.C8(DQ13)
DDR_DQ12: U27.T22(DDR_DQ12) U29.D3(DQ14)
DDR_DQ13: U27.R20(DDR_DQ13) U29.C3(DQ10)
DDR_DQ14: U27.R21(DDR_DQ14) U29.C2(DQ12)
DDR_DQ15: U27.R22(DDR_DQ15) U29.A3(DQ8)
DDR_DQ16: U27.D20(DDR_DQ16) U28.D7(DQ15)
DDR_DQ17: U27.C22(DDR_DQ17) U28.C7(DQ11)
DDR_DQ18: U27.C21(DDR_DQ18) U28.B8(DQ9)
DDR_DQ19: U27.B22(DDR_DQ19) U28.C8(DQ13)
DDR_DQ20: U27.F20(DDR_DQ20) U28.D3(DQ14)
DDR_DQ21: U27.F19(DDR_DQ21) U28.C3(DQ10)
DDR_DQ22: U27.E19(DDR_DQ22) U28.C2(DQ12)
DDR_DQ23: U27.E20(DDR_DQ23) U28.A3(DQ8)
DDR_DQ24: U27.G19(DDR_DQ24) U28.J3(DQ6)
DDR_DQ25: U27.G22(DDR_DQ25) U28.H2(DQ4)
DDR_DQ26: U27.G21(DDR_DQ26) U28.H3(DQ2)
DDR_DQ27: U27.G20(DDR_DQ27) U28.G2(DQ0)
DDR_DQ28: U27.J21(DDR_DQ28) U28.J7(DQ7)
DDR_DQ29: U27.J20(DDR_DQ29) U28.H8(DQ5)
DDR_DQ30: U27.K20(DDR_DQ30) U28.H7(DQ3)
DDR_DQ31: U27.L19(DDR_DQ31) U28.F7(DQ1)
DDR_DQM0: U27.W21(DDR_DQM0) U29.E7(LDM_n/LDBI_n)
DDR_DQM1: U27.P20(DDR_DQM1) U29.E2(UDM_n/UDBI_n)
DDR_DQM2: U27.E21(DDR_DQM2) U28.E2(UDM_n/UDBI_n)
DDR_DQM3: U27.H20(DDR_DQM3) U28.E7(LDM_n/LDBI_n)
DDR_DQS0_N: U27.W20(DDR_DQS0N) U29.F3(LDQS_c)
DDR_DQS0_P: U27.V20(DDR_DQS0P) U29.G3(LDQS_t)
DDR_DQS1_N: U27.N21(DDR_DQS1N) U29.A7(UDQS_c)
DDR_DQS1_P: U27.N20(DDR_DQS1P) U29.B7(UDQS_t)
DDR_DQS2_N: U27.D22(DDR_DQS2N) U28.A7(UDQS_c)
DDR_DQS2_P: U27.D21(DDR_DQS2P) U28.B7(UDQS_t)
DDR_DQS3_N: U27.H21(DDR_DQS3N) U28.F3(LDQS_c)
DDR_DQS3_P: U27.H22(DDR_DQS3P) U28.G3(LDQS_t)
DDR_ODT: R258.1 U27.M17(DDR_A3) U28.K3(ODT) U29.K3(ODT)
DDR_RASN: R276.1 U27.N17(DDR_A11) U28.L8(RAS_n/A16) U29.L8(RAS_n/A16)
DDR_RESETN: R252.2 U27.F18(DDR_RESETN) U28.P1(RESET_n) U29.P1(RESET_n)
DDR_WEN: R257.1 U27.G18(DDR_A20) U28.L2(WE_n//A14) U29.L2(WE_n//A14)
NetR63_2: R63.2 U28.F9(ZQ)
NetR73_2: R73.2 U29.F9(ZQ)
NetR262_2: R262.2 U27.K16(DDR_ZQ)
NetTP10_1: TP10.1 U27.L20(DDR_VREF)

Not connected (* = marked no-connect by the designer): U27 J18(DDR_A16)* K17(DDR_A19)* T18(DDR_A6)* U18(DDR_A1)* U19(DDR_A7)*; U28 P9(ALERT_n)* T7(NC)*; U29 P9(ALERT_n)* T7(NC)*

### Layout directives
differential pair: DDR_CLK_N, DDR_CLK_P, DDR_DQS0_N, DDR_DQS0_P, DDR_DQS1_N, DDR_DQS1_P, DDR_DQS2_N, DDR_DQS2_P, DDR_DQS3_N, DDR_DQS3_P

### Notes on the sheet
- Title:
- Project:
- Size:
- Revision:
- Variant:
- A3
- -
- Date:
- Reference:
- Sheet:
- of

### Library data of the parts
C48-C51 C77-C80 C82-C84 C93-C95 C184-C187 C189 C198 C202 C211 C226 C238 C239 C245 C247 C255-C259 C261 C262 C264 = MCD-00006: Capacitor, MLCC, 100nF, 16V, X7R, +/-10%, 0402, T=0.5mm; Part_Preference: Recommended; Manufacturer: YAGEO; Manufacturer_Part_Number: CC0402KRX7R7BB104; Alternate_Manufacturer: MURATA; Alternate_Manufacturer_Part_Number: GCM155R71C104KA55D; Partial_Alternate_Internal_Part_Number: MCD-03299; Order_Code_RS: 9402047; Component_Country_Of_Origin: China; ID: 2474; ShowFields: YES
C85 C99 C188 C236 = MCD-01341: Capacitor, MLCC, 10uF, 6V3, X5R, +/-20%, 0603, T=0,8mm; Part_Preference: Recommended; Manufacturer: MURATA; Manufacturer_Part_Number: GRM188R60J106ME47; Alternate_Manufacturer_Part_Number: GRM188R60J106ME84D; Partial_Alternate_Internal_Part_Number: MCD-04454; Component_Country_Of_Origin: Japan°°; ID: 3441; ShowFields: YES
C183 C254 = MCD-00099: Capacitor, MLCC, 10uF, 10V, X5R, +/-10%, 0603, T=0.8mm; Part_Preference: Recommended; Manufacturer: MURATA; Manufacturer_Part_Number: GRM188R61A106KE69; Partial_Alternate_Internal_Part_Number: MCD-03152; Order_Code_RS: 2494233; Component_Country_Of_Origin: Japan°°; ShowFields: YES; ID: 2770
R63 R73 R262 = MCD-02253: Resistor,240R,0201,1%,1/20W; Part_Preference: Recommended; Manufacturer: YAGEO; Manufacturer_Part_Number: RC0201FR-07240RL; Component_Country_Of_Origin: China; ID: 4353; ShowFields: YES
R252 = MCD-00053: Resistor,10K,0402,1%,1/16W; BMS_Part_Number: 9131590; Part_Preference: Recommended; Manufacturer: YAGEO; Manufacturer_Part_Number: RC0402FR-0710KL; Order_Code_RS: 9239359; Component_Country_Of_Origin: China; ID: 2539; ShowFields: YES
R253-R259 R263-R266 R268 R271 R273 R275-R284 = MCD-00054: Resistor, 56R, 0402, +/-1%, 1/16W; Part_Preference: Recommended; Manufacturer: YAGEO; Manufacturer_Part_Number: RC0402FR-0756RL; Order_Code_RS: 9239081; Component_Country_Of_Origin: China; ID: 2538; ShowFields: YES
R270 = MCD-01819: Resistor,100R,0402,0,5%,1/16W,±100ppm/°C; Part_Preference: Recommended; Manufacturer: YAGEO; Manufacturer_Part_Number: RC0402DR-07100RL; Component_Country_Of_Origin: China; ID: 3919; ShowFields: YES
TP10 = MCD-00631: Test Point 0.6mm; Part_Type: Misc; Part_Preference: Recommended; Component_Country_Of_Origin: Unknown; ID: 3108; ShowFields: YES
U27 = MCD-02000: as U27 on sheet Power_MPU
U28 U29 = MCD-03523: Memory, DDR4 SDRAM, 1V2, 16Gbit, FBGA96; Part_Type: IC; Part_Preference: Not recommended; Manufacturer: MICRON; Component_Country_Of_Origin: Taiwan°; ShowFields: YES; ID: 5639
